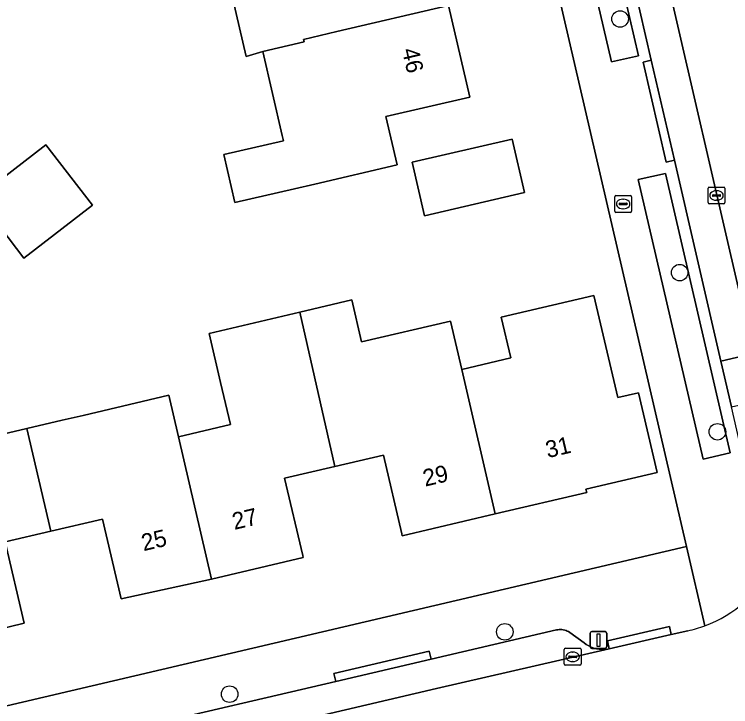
# Model space of a CAD drawing. Extents: x 157320 to 158835, y 386650 to 388491.
# Drawn here: x 157689.7 to 157732.07, y 387829.62 to 387870.56 of the extents above; entities that cross this region are included whole.
import ezdxf

# ---------------------------------------------------------------- set-up
doc = ezdxf.new("R2010")
doc.units = 0
for name, color, linetype in [('IMGEO_Boom', 7, 'Continuous'), ('IMGEO_Brandkraan', 7, 'Continuous'), ('IMGEO_Erf', 7, 'Continuous'), ('IMGEO_Groenvoorziening', 7, 'Continuous'), ('IMGEO_Kolk', 7, 'Continuous'), ('IMGEO_Lichtmast', 7, 'Continuous'), ('IMGEO_Pand', 7, 'Continuous'), ('IMGEO_Pand_nummerreeks', 7, 'Continuous'), ('IMGEO_Parkeervlak_open', 7, 'Continuous'), ('IMGEO_Rijbaan_lokaal_open', 7, 'Continuous'), ('IMGEO_Voetpad_open', 7, 'Continuous')]:
    doc.layers.add(name, color=color, linetype=linetype)

msp = doc.modelspace()

# ---------------------------------------------------------------- linework, layer by layer
at = {"layer": 'IMGEO_Boom'}
for centre in [(157725.532, 387870.289), (157729.06, 387855.288), (157731.29, 387845.874), (157718.713, 387834.041), (157702.435, 387830.355)]:
    msp.add_circle(centre, 0.489, dxfattribs=at)
at = {"layer": 'IMGEO_Brandkraan'}
for p, q in [((157725.213, 387858.922), (157725.213, 387859.774)), ((157725.288, 387859.848), (157726.14, 387859.848)), ((157726.214, 387859.774), (157726.214, 387858.922)), ((157725.472, 387859.342), (157725.472, 387859.354)), ((157725.91, 387859.305), (157725.512, 387859.305)), ((157725.515, 387859.391), (157725.913, 387859.391)), ((157725.701, 387859.628), (157725.726, 387859.628)), ((157725.956, 387859.354), (157725.956, 387859.342)), ((157726.14, 387858.848), (157725.288, 387858.848)), ((157725.724, 387859.068), (157725.699, 387859.068))]:
    msp.add_line(p, q, dxfattribs=at)
for points in [[(157725.213, 387858.922), (157725.213, 387859.774)], [(157725.288, 387859.848), (157726.14, 387859.848)], [(157726.214, 387859.774), (157726.214, 387858.922)], [(157726.14, 387858.848), (157725.288, 387858.848)]]:
    msp.add_lwpolyline(points, dxfattribs=at)
for centre, radius, start, end in [((157725.29, 387859.772), 0.0765, 91.552, 178.448), ((157725.29, 387859.772), 0.0765, 91.552, 178.448), ((157726.138, 387859.772), 0.0765, 1.552, 88.448), ((157726.138, 387859.772), 0.0765, 1.552, 88.448), ((157725.512, 387859.351), 0.0403, 85.8775, 175.7526), ((157725.509, 387859.341), 0.0366, 178.938, 274.7102), ((157725.913, 387859.348), 0.043, 264.8664, 352.4533), ((157725.917, 387859.353), 0.0386, 1.7309, 96.639), ((157725.29, 387858.924), 0.0765, 181.552, 268.448), ((157725.29, 387858.924), 0.0765, 181.552, 268.448), ((157726.138, 387858.924), 0.0765, 271.552, 358.448), ((157726.138, 387858.924), 0.0765, 271.552, 358.448)]:
    msp.add_arc(centre, radius, start, end, dxfattribs=at)
for centre, major_axis, ratio, start_param, end_param in [((157725.7, 387859.348), (-0.387, 0.002), 0.722429, 4.712389, 7.853982), ((157725.725, 387859.348), (-0.39, 0.002), 0.717154, 1.570796, 4.712389)]:
    msp.add_ellipse(centre, major_axis=major_axis, ratio=ratio, start_param=start_param, end_param=end_param, dxfattribs=at)
at = {"layer": 'IMGEO_Erf'}
for points in [[(157611.28, 387905.251), (157676.491, 387831.375), (157676.979, 387830.83), (157677.515, 387830.331), (157678.092, 387829.881), (157678.708, 387829.485), (157679.356, 387829.145), (157680.033, 387828.865), (157680.731, 387828.646), (157681.446, 387828.491), (157682.173, 387828.4), (157682.904, 387828.374), (157683.635, 387828.414), (157684.359, 387828.519), (157684.789, 387828.613), (157729.457, 387839.094), (157721.261, 387874.483)], [(157715.38, 387871.087), (157716.636, 387865.665), (157711.685, 387864.518), (157712.348, 387861.655), (157707.477, 387860.527), (157706.278, 387860.249), (157702.751, 387859.431), (157702.095, 387862.264), (157705.622, 387863.08), (157705.549, 387863.398), (157704.399, 387868.366), (157703.422, 387868.067), (157702.177, 387873.441)], [(157687.657, 387845.414), (157690.447, 387846.067), (157692.526, 387846.554), (157693.768, 387846.845), (157698.832, 387848.031), (157699.404, 387845.581), (157702.483, 387846.302), (157701.899, 387848.793), (157701.219, 387851.692), (157706.591, 387852.95), (157709.66, 387853.669), (157710.24, 387851.189), (157715.494, 387852.419), (157716.175, 387849.562), (157719.069, 387850.24), (157718.504, 387852.65), (157723.977, 387853.932), (157725.39, 387847.894), (157726.614, 387848.181), (157727.72, 387843.458), (157723.512, 387842.472), (157723.558, 387842.277), (157718.152, 387841.011), (157712.65, 387839.722), (157712.623, 387839.839), (157711.532, 387844.499), (157708.653, 387843.825), (157705.684, 387843.129), (157706.757, 387838.55), (157706.784, 387838.433), (157701.37, 387837.165), (157696.014, 387836.003), (157694.913, 387840.71), (157691.851, 387839.993), (157689.16, 387839.362), (157690.285, 387834.558), (157684.618, 387833.182)]]:
    msp.add_lwpolyline(points, dxfattribs=at)
for points in [[(157719.143, 387863.189), (157719.877, 387860.018), (157713.973, 387858.651), (157713.239, 387861.822)], [(157691.569, 387862.849), (157694.326, 387859.269), (157690.271, 387856.146), (157687.514, 387859.725)]]:
    msp.add_lwpolyline(points, close=True, dxfattribs=at)
at = {"layer": 'IMGEO_Groenvoorziening'}
for points in [[(157725.031, 387867.75), (157726.617, 387868.118), (157725.338, 387873.639), (157723.753, 387873.271)], [(157730.441, 387844.258), (157732.041, 387844.629), (157728.213, 387861.158), (157726.612, 387860.787)]]:
    msp.add_lwpolyline(points, close=True, dxfattribs=at)
at = {"layer": 'IMGEO_Kolk'}
for p, q in [((157730.737, 387859.425), (157730.737, 387860.277)), ((157730.812, 387860.351), (157731.664, 387860.351)), ((157731.225, 387860.131), (157731.25, 387860.131)), ((157731.738, 387860.277), (157731.738, 387859.425)), ((157730.996, 387859.845), (157730.996, 387859.857)), ((157731.434, 387859.808), (157731.036, 387859.808)), ((157731.039, 387859.894), (157731.437, 387859.894)), ((157731.48, 387859.857), (157731.48, 387859.845)), ((157731.664, 387859.351), (157730.812, 387859.351)), ((157731.248, 387859.571), (157731.223, 387859.571)), ((157722.23, 387832.14), (157722.23, 387832.992)), ((157722.305, 387833.066), (157723.157, 387833.066)), ((157723.231, 387832.992), (157723.231, 387832.14)), ((157722.489, 387832.56), (157722.489, 387832.572)), ((157722.927, 387832.523), (157722.529, 387832.523)), ((157722.532, 387832.609), (157722.93, 387832.609)), ((157722.718, 387832.846), (157722.743, 387832.846)), ((157722.973, 387832.572), (157722.973, 387832.56)), ((157722.741, 387832.286), (157722.716, 387832.286)), ((157723.157, 387832.066), (157722.305, 387832.066))]:
    msp.add_line(p, q, dxfattribs=at)
for points in [[(157730.737, 387859.425), (157730.737, 387860.277)], [(157730.812, 387860.351), (157731.664, 387860.351)], [(157731.738, 387860.277), (157731.738, 387859.425)], [(157731.664, 387859.351), (157730.812, 387859.351)], [(157722.23, 387832.14), (157722.23, 387832.992)], [(157722.305, 387833.066), (157723.157, 387833.066)], [(157723.231, 387832.992), (157723.231, 387832.14)], [(157723.157, 387832.066), (157722.305, 387832.066)]]:
    msp.add_lwpolyline(points, dxfattribs=at)
for centre, radius, start, end in [((157730.814, 387860.275), 0.0765, 91.552, 178.448), ((157730.814, 387860.275), 0.0765, 91.552, 178.448), ((157731.662, 387860.275), 0.0765, 1.552, 88.448), ((157731.662, 387860.275), 0.0765, 1.552, 88.448), ((157731.036, 387859.854), 0.0403, 85.8775, 175.7526), ((157731.033, 387859.844), 0.0366, 178.938, 274.7102), ((157731.437, 387859.851), 0.043, 264.8664, 352.4533), ((157731.441, 387859.856), 0.0386, 1.7309, 96.639), ((157730.814, 387859.427), 0.0765, 181.552, 268.448), ((157730.814, 387859.427), 0.0765, 181.552, 268.448), ((157731.662, 387859.427), 0.0765, 271.552, 358.448), ((157731.662, 387859.427), 0.0765, 271.552, 358.448), ((157722.307, 387832.99), 0.0765, 91.552, 178.448), ((157722.307, 387832.99), 0.0765, 91.552, 178.448), ((157723.155, 387832.99), 0.0765, 1.552, 88.448), ((157723.155, 387832.99), 0.0765, 1.552, 88.448), ((157722.529, 387832.569), 0.0403, 85.8775, 175.7526), ((157722.526, 387832.559), 0.0366, 178.938, 274.7102), ((157722.93, 387832.566), 0.043, 264.8664, 352.4533), ((157722.934, 387832.571), 0.0386, 1.7309, 96.639), ((157722.307, 387832.142), 0.0765, 181.552, 268.448), ((157722.307, 387832.142), 0.0765, 181.552, 268.448), ((157723.155, 387832.142), 0.0765, 271.552, 358.448), ((157723.155, 387832.142), 0.0765, 271.552, 358.448)]:
    msp.add_arc(centre, radius, start, end, dxfattribs=at)
for centre, major_axis, ratio, start_param, end_param in [((157731.224, 387859.851), (-0.387, 0.002), 0.722429, 4.712389, 7.853982), ((157731.249, 387859.851), (-0.39, 0.002), 0.717154, 1.570796, 4.712389), ((157722.717, 387832.566), (-0.387, 0.002), 0.722429, 4.712389, 7.853982), ((157722.742, 387832.566), (-0.39, 0.002), 0.717154, 1.570796, 4.712389)]:
    msp.add_ellipse(centre, major_axis=major_axis, ratio=ratio, start_param=start_param, end_param=end_param, dxfattribs=at)
at = {"layer": 'IMGEO_Lichtmast'}
for p, q in [((157723.758, 387833.158), (157723.758, 387833.958)), ((157723.758, 387833.958), (157723.758, 387833.158)), ((157723.858, 387834.058), (157724.648, 387834.058)), ((157724.648, 387834.058), (157723.858, 387834.058)), ((157724.748, 387833.958), (157724.748, 387833.158)), ((157724.748, 387833.158), (157724.748, 387833.958)), ((157724.648, 387833.058), (157723.858, 387833.058)), ((157723.858, 387833.058), (157724.648, 387833.058))]:
    msp.add_line(p, q, dxfattribs=at)
msp.add_lwpolyline([(157724.178, 387833.933), (157724.328, 387833.933), (157724.328, 387833.183), (157724.178, 387833.183), (157724.178, 387833.933)], dxfattribs=at)
for centre, start, end in [((157723.858, 387833.958), 90, 180), ((157723.858, 387833.958), 90, 180), ((157724.648, 387833.958), 0, 90), ((157724.648, 387833.958), 360, 90), ((157723.858, 387833.158), 180, 270), ((157723.858, 387833.158), 180, 270), ((157724.648, 387833.158), 270, 0), ((157724.648, 387833.158), 270, 0)]:
    msp.add_arc(centre, 0.1, start, end, dxfattribs=at)
at = {"layer": 'IMGEO_Pand'}
for points in [[(157714.105, 387876.591), (157708.664, 387875.331), (157707.661, 387879.665), (157701.976, 387876.753), (157700.078, 387875.575), (157700.655, 387873.089), (157702.177, 387873.441), (157703.422, 387868.067), (157704.399, 387868.366), (157706.836, 387868.93), (157706.801, 387869.082), (157708.771, 387869.542), (157715.38, 387871.087)], [(157715.38, 387871.087), (157708.771, 387869.542), (157706.801, 387869.082), (157706.836, 387868.93), (157704.399, 387868.366), (157705.549, 387863.398), (157705.622, 387863.08), (157702.095, 387862.264), (157702.751, 387859.431), (157706.278, 387860.249), (157707.477, 387860.527), (157712.348, 387861.655), (157711.685, 387864.518), (157716.636, 387865.665)], [(157713.973, 387858.651), (157719.877, 387860.018), (157719.143, 387863.189), (157713.239, 387861.822)], [(157687.514, 387859.725), (157690.271, 387856.146), (157694.326, 387859.269), (157691.569, 387862.849)], [(157716.175, 387849.562), (157718.152, 387841.011), (157723.558, 387842.277), (157723.512, 387842.472), (157727.72, 387843.458), (157726.614, 387848.181), (157725.39, 387847.894), (157723.977, 387853.932), (157718.504, 387852.65), (157719.069, 387850.24)], [(157716.175, 387849.562), (157715.494, 387852.419), (157710.24, 387851.189), (157709.66, 387853.669), (157706.591, 387852.95), (157708.653, 387843.825), (157711.532, 387844.499), (157712.623, 387839.839), (157712.65, 387839.722), (157718.152, 387841.011)], [(157706.591, 387852.95), (157701.219, 387851.692), (157701.899, 387848.793), (157702.483, 387846.302), (157699.404, 387845.581), (157701.37, 387837.165), (157706.784, 387838.433), (157706.757, 387838.55), (157705.684, 387843.129), (157708.653, 387843.825)], [(157699.404, 387845.581), (157698.832, 387848.031), (157693.768, 387846.845), (157692.526, 387846.554), (157690.447, 387846.067), (157691.851, 387839.993), (157694.913, 387840.71), (157696.014, 387836.003), (157701.37, 387837.165)], [(157691.851, 387839.993), (157690.447, 387846.067), (157687.657, 387845.414), (157687.529, 387845.961), (157682.161, 387844.704), (157681.926, 387844.649), (157684.618, 387833.182), (157690.285, 387834.558), (157689.16, 387839.362)]]:
    msp.add_lwpolyline(points, close=True, dxfattribs=at)
at = {"layer": 'IMGEO_Parkeervlak_open'}
for points in [[(157726.026, 387873.703), (157727.379, 387867.852), (157728.746, 387861.938), (157731.495, 387850.051), (157733.418, 387850.495), (157727.376, 387876.71)], [(157683.612, 387823.423), (157714.68, 387830.684), (157724.892, 387833.031), (157724.799, 387833.015), (157724.634, 387833), (157724.469, 387832.999), (157724.305, 387833.013), (157724.142, 387833.041), (157723.983, 387833.084), (157723.828, 387833.141), (157723.679, 387833.211), (157723.536, 387833.295), (157723.402, 387833.391), (157722.554, 387834.007), (157722.484, 387834.052), (157722.411, 387834.091), (157722.335, 387834.124), (157722.255, 387834.149), (157722.174, 387834.167), (157722.092, 387834.178), (157722.009, 387834.181), (157721.926, 387834.178), (157721.844, 387834.166), (157721.776, 387834.151), (157714.354, 387832.418), (157708.714, 387831.101), (157696.877, 387828.336)]]:
    msp.add_lwpolyline(points, dxfattribs=at)
msp.add_lwpolyline([(157732.121, 387847.342), (157734.043, 387847.785), (157733.418, 387850.495), (157731.495, 387850.051)], close=True, dxfattribs=at)
at = {"layer": 'IMGEO_Rijbaan_lokaal_open'}
for points in [[(157729.55, 387834.104), (157728.562, 387833.876), (157724.892, 387833.031), (157714.68, 387830.684), (157683.612, 387823.423), (157683.417, 387823.394), (157683.222, 387823.368), (157682.956, 387823.339), (157682.032, 387823.293), (157681.107, 387823.329), (157680.189, 387823.447), (157679.285, 387823.647), (157678.403, 387823.927), (157677.549, 387824.285), (157676.731, 387824.718), (157675.955, 387825.222), (157675.226, 387825.793), (157674.552, 387826.427), (157673.92, 387827.143), (157608.833, 387900.938)], [(157725.156, 387882.855), (157726.116, 387880.486), (157726.522, 387879.32), (157727.376, 387876.71), (157733.418, 387850.495), (157739.225, 387851.835), (157735.396, 387868.179), (157735.29, 387868.665), (157734.718, 387871.279), (157732.8, 387879.908)]]:
    msp.add_lwpolyline(points, dxfattribs=at)
for centre, radius, start, end in [((157727.992, 387841.296), 7.358, 290.3097, 14.9569), ((157727.977, 387841.339), 7.404, 282.2685, 290.3049)]:
    msp.add_arc(centre, radius, start, end, dxfattribs=at)
at = {"layer": 'IMGEO_Voetpad_open'}
for points in [[(157721.261, 387874.483), (157729.457, 387839.094), (157730.546, 387834.395)], [(157732.598, 387845.278), (157732.121, 387847.342), (157731.495, 387850.051), (157728.746, 387861.938), (157728.259, 387861.826), (157726.892, 387867.74), (157727.379, 387867.852), (157726.026, 387873.703)], [(157729.457, 387839.094), (157684.789, 387828.613)], [(157730.546, 387834.395), (157729.457, 387839.094)], [(157696.877, 387828.336), (157708.714, 387831.101), (157708.6, 387831.587), (157714.24, 387832.904), (157714.354, 387832.418), (157721.776, 387834.151), (157721.844, 387834.166), (157721.926, 387834.178), (157722.009, 387834.181), (157722.092, 387834.178), (157722.174, 387834.167), (157722.255, 387834.149), (157722.335, 387834.124), (157722.411, 387834.091), (157722.484, 387834.052), (157722.554, 387834.007), (157723.402, 387833.391), (157723.536, 387833.295), (157723.679, 387833.211), (157723.828, 387833.141), (157723.983, 387833.084), (157724.142, 387833.041), (157724.305, 387833.013), (157724.469, 387832.999), (157724.634, 387833), (157724.799, 387833.015), (157724.892, 387833.031), (157724.78, 387833.518), (157728.45, 387834.363), (157728.562, 387833.876), (157729.55, 387834.104)]]:
    msp.add_lwpolyline(points, dxfattribs=at)
for points in [[(157725.031, 387867.75), (157723.753, 387873.271), (157725.338, 387873.639), (157726.617, 387868.118)], [(157728.746, 387861.938), (157727.379, 387867.852), (157726.892, 387867.74), (157728.259, 387861.826)], [(157730.441, 387844.258), (157726.612, 387860.787), (157728.213, 387861.158), (157732.041, 387844.629)], [(157724.892, 387833.031), (157728.562, 387833.876), (157728.45, 387834.363), (157724.78, 387833.518)], [(157708.714, 387831.101), (157714.354, 387832.418), (157714.24, 387832.904), (157708.6, 387831.587)]]:
    msp.add_lwpolyline(points, close=True, dxfattribs=at)
for centre, radius, start, end in [((157727.992, 387841.296), 7.358, 290.3097, 14.9569), ((157727.977, 387841.339), 7.404, 282.2685, 290.3049)]:
    msp.add_arc(centre, radius, start, end, dxfattribs=at)

# ---------------------------------------------------------------- texts
at = {"layer": 'IMGEO_Pand_nummerreeks'}
for s, rotation, p in [('46', 283.0403, (157712.622, 387868.461)), ('31', 13.1828, (157721.251, 387844.31)), ('29', 13.1838, (157713.999, 387842.626)), ('27', 13.1841, (157702.717, 387840.069)), ('25', 13.1838, (157697.344, 387838.81))]:
    msp.add_text(s, height=1, rotation=rotation, dxfattribs=at).set_placement(p)

doc.saveas('drawing.dxf')
